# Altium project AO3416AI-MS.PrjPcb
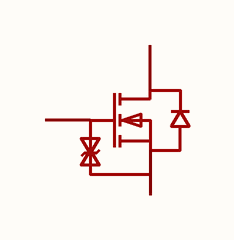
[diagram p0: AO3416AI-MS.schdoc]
1 sheet, 1 parts. Net scope: global (net labels, ports and power ports of the same name join across sheets).

## Sheet AO3416AI-MS.schdoc
size 127 x 101 mm

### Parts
Q?  ao3416ai-ms  [SOT-23-3_L2.9-W1.3-P1.90-LS2.4-BR]  (value not drawn)

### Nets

Not connected (* = marked no-connect by the designer): Q? 1(G) 2(S) 3(D)

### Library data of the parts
Q? = ao3416ai-ms: 数量:1个N沟道;漏源电压(Vdss):20V;连续漏极电流(Id):6A;导通电阻(RDS(on)):14mΩ@4.5V;耗散功率(Pd):1.4W;阈值电压(Vgs(th)):700mV@250uA;; Manufacturer: MSKSEMI(美森科); AddInBom: yes; ModelId: c62791f0466c4ae2a892c056b845b0ca; ModelName: SOT-23-3P_L2.9-W1.3-H1.0-LS2.4-P0.95; ModelTransform: 98.425,114.173,0,180,0,0,0.0005,-0.0005,0; Number: 1个N沟道; Drain to Source Voltage: 20V; Current - Continuous Drain(Id): 6A; Pd - Power Dissipation: 1.4W; Gate Charge(Qg): 8nC@4.5V; Input Capacitance(Ciss): 660pF; Reverse Transfer Capacitance (Crss@Vds): 87pF; Type: N沟道; Output Capacitance(Coss): 160pF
